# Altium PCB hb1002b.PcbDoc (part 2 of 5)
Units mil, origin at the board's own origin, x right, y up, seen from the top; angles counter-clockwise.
Board outline 2756 x 3549 mil, 2 copper layers (Top Layer, Bottom Layer); 120 components, 136 nets, 498 pads, 328 vias.
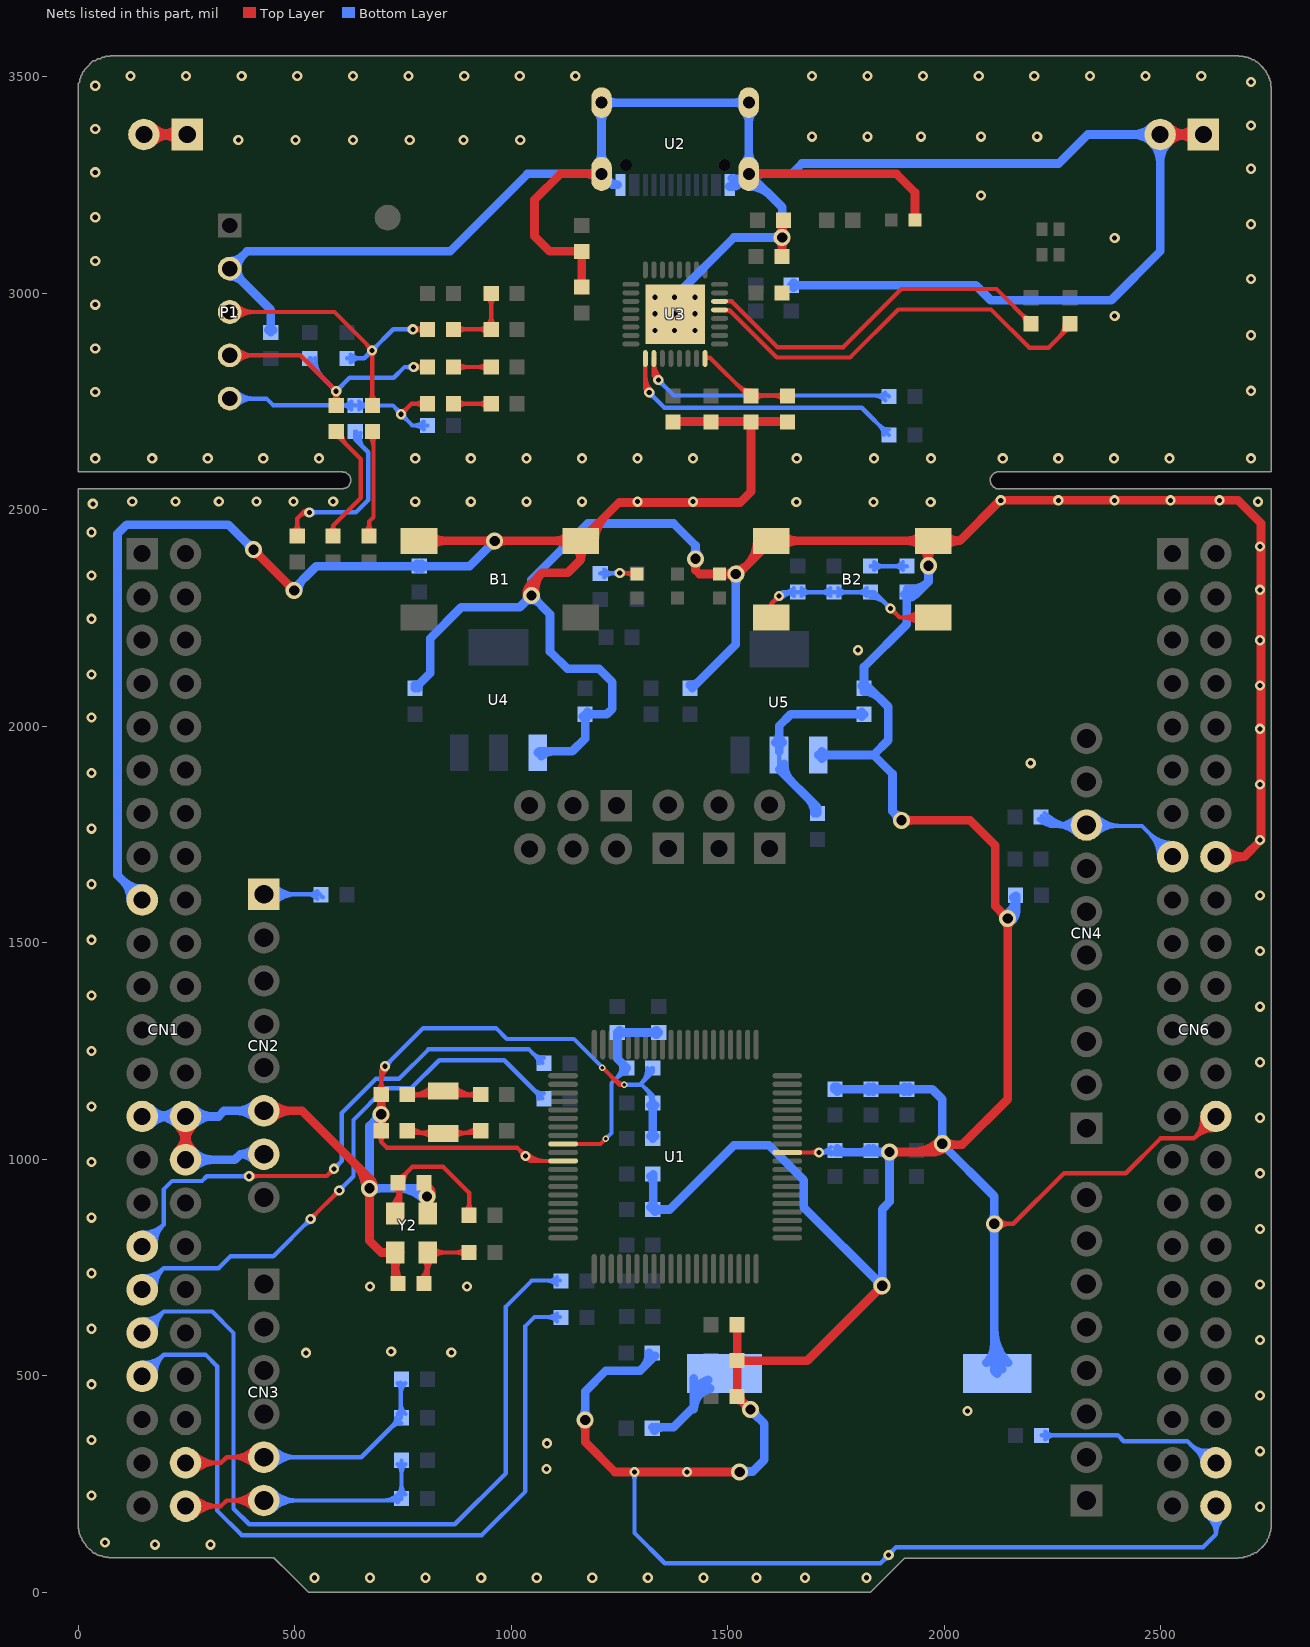
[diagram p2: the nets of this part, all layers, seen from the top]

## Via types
v1: diameter 23.62, hole 11.81, Top Layer to Bottom Layer, tented both sides, 276 vias
v2: diameter 39.37, hole 23.62, Top Layer to Bottom Layer, tented both sides, 27 vias
v3: diameter 15, hole 8, Top Layer to Bottom Layer, tented both sides, 25 vias

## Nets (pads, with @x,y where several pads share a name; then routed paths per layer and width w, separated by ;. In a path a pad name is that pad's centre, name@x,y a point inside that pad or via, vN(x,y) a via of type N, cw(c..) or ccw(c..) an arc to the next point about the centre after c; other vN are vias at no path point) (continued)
GND: B1.1 B1.2 B2.1 B2.2 BT1.2 C1.1 C2.2 C3.1 C4.2 C5.1 C6.1 C9.2 C11.2 C12.2 C13.2 C14.2 C15.2 C16.2 C17.2 C18.2 C19.2 C20.1 C21.1 C22.1 C23.1 C24.1 C25.1 C26.1 C27.1 C28.1 C29.2 C30.2 C31.1 C32.2 C34.1 C35.2 C36.2 CN1.17 CN1.27 CN1.28 CN1.30 CN2.6 CN2.7 CN6.16 CN6.28 CN6.46 D3.2 D4.2 JP2.1 JP2.2 JP3.1 JP3.2 P1.2 R5.2 R11.2 R25.2 R28.1 U1.11 U1.51 U2.1 U2.2 U2.3 U2.4 U2.A1 U2.A12 U2.B1 U2.B12 U3.33 U4.1 U5.1 Y2.2 Y2.4 | length 32956.4
  Top Layer w10: CN1.30@248,999 CN1.30@251,996 ; CN2.7@424,996 CN2.7@428,1000 ; C5.1@691.16,1158.84 ccw(c669.82,1180.18) 700,1180.18 ccw(c730.18,1180.18) C5.1@708.84,1158.84 ; C6.1@692.19,1056.24 cw(c679.21,1040) 700,1040 ; C6.1@700,1056 700,1040 ; C5.1@700,1140 C5.1@700,1150 700,1206 v1(709,1215) v1@709,1219 ; 700,1176.83 cw(c747.17,1176.83) v1@713.82,1210.18 ; 700,1200.97 cw(c723.03,1200.97) v1@706.75,1217.25 ; C6.1@707.81,1056.24 ccw(c720.79,1040) 700,1040 ; Y2.4@810,883.68 Y2.4@818.4,875.28 ; v1@1026.19,1008 ccw(c1009.75,1008) 1021.37,1019.63 ccw(c1033,1031.25) v1@1033,1014.81 ; v1@1030.75,1005.75 ccw(c1053.89,1028.89) 1053.89,996.16 ; v1@1033,1001.19 cw(c1033,984.75) 1044.63,996.37 cw(c1056.25,1008) v1@1039.81,1008 ; v1@1037.82,1012.82 ccw(c1078.03,1053.03) 1078.03,996.16 ; U1.11@1120.14,996.16 1044.84,996.16 v1(1033,1008) 1013.9,1027.1 712.9,1027.1 700,1040 ; B1.2@1155.58,2428.58 B1.2@1161.01,2428.58 ; B1.2@1173.58,2428.58 B1.2@1174.58,2428.58 ; v3(1211,1212) 1251,1172 v3(1261,1172) ; 1239.66,1183.34 ccw(c1261,1204.68) v3@1261,1174.5 ; U1.51@1637.86,1015.84 v1@1711,1015.84 ; 1694.18,1015.84 ccw(c1694.18,1032.82) v1@1706.18,1020.82 ; 1694.94,1015.84 cw(c1694.94,999.94) v1@1706.18,1011.18 ; v2(2116,851) 2160,851 2277,968 2419.58,968 2500,1048.42 2577.42,1048.42 ; v2@2126.38,840.62 cw(c2151.45,815.55) 2151.45,851 cw(c2151.45,886.45) v2@2126.38,861.38 ; CN6.28@2596.61,1097.67 cw(c2530.95,1094.89) 2577.42,1048.42 ; CN6.28@2606.6,1098.09 cw(c2561.84,1096.2) 2593.52,1064.52 cw(c2625.2,1032.84) CN6.28@2627.09,1077.6 ; CN6.28@2626.67,1067.61 ccw(c2623.89,1001.95) 2577.42,1048.42 ; CN6.28@2628,1099 2577.42,1048.42
  Top Layer w20: JP3.2@152,3367 JP3.1@252,3367 ; JP3.2@170.68,3348.32 cw(c215.78,3303.22) 215.78,3367 cw(c215.78,3430.78) JP3.2@170.68,3385.68 ; CN1.30@229.32,1017.68 ccw(c184.22,1062.78) 248,1062.78 ccw(c311.78,1062.78) CN1.30@266.68,1017.68 ; CN1.28@229.32,1080.32 cw(c184.22,1035.22) 248,1035.22 cw(c311.78,1035.22) CN1.28@266.68,1080.32 ; JP3.1@233.32,3348.32 ccw(c188.22,3303.22) 188.22,3367 ccw(c188.22,3430.78) JP3.1@233.32,3385.68 ; CN1.30@248,999 CN1.28@248,1099 ; v2@405,2398.31 cw(c405,2374.93) 421.53,2391.47 cw(c438.07,2408) v2@414.69,2408 ; v2(405,2408) v2(499,2314) ; CN2.6@429,1112 517,1112 673,956 ; CN2.6@447.68,1093.32 cw(c492.78,1048.22) 492.78,1112 cw(c492.78,1175.78) CN2.6@447.68,1130.68 ; v2@489.31,2314 ccw(c465.93,2314) 482.47,2330.53 ccw(c499,2347.07) v2@499,2323.69 ; 640.2,988.8 cw(c584.41,933) v2@663.31,933 ; v2@666.15,926.15 cw(c649.62,909.62) 673,909.62 cw(c696.38,909.62) v2@679.85,926.15 ; v2@666.23,939.93 ccw(c650.54,956) 673,956 ; 674.35,954.65 cw(c652.69,933) v2@683.32,933 ; v2@679.77,939.93 cw(c695.46,956) 673,956 ; v2@693.15,1097.15 cw(c676.62,1080.62) 700,1080.62 cw(c723.38,1080.62) v2@706.85,1097.15 ; v2@693.15,1110.85 ccw(c676.62,1127.38) 700,1127.38 ccw(c723.38,1127.38) v2@706.85,1110.85 ; C6.1@694.7,1071.3 ccw(c681.89,1084.11) 700,1084.11 ccw(c718.11,1084.11) C6.1@705.3,1071.3 ; C5.1@694.7,1144.7 cw(c681.89,1131.89) 700,1131.89 cw(c718.11,1131.89) C5.1@705.3,1144.7 ; C6.1@700,1056 C6.1@700,1066 C5.1@700,1140 ; Y2.2@724.36,772.55 cw(c704.46,752.65) 732.6,752.65 cw(c760.73,752.65) Y2.2@740.84,772.55 ; Y2.2@724.36,776.48 ccw(c704.46,756.59) 704.46,784.72 ccw(c704.46,812.86) Y2.2@724.36,792.96 ; 732.6,746.56 ccw(c772.56,746.56) C12.2@744.3,718.3 ; C12.2@739,713 732.6,719.4 Y2.2@732.6,784.72 ; Y2.2@743.6,784.72 Y2.2@732.6,784.72 ; B1.1@786.99,2428.58 B1.2@1155.58,2428.58 ; C11.2@793.7,940.7 cw(c763.03,910.03) v2@806.4,910.03 ; C11.2@799,946 C11.2@807.4,937.6 ; Y2.4@799.16,887.45 ccw(c781.68,904.93) v2@806.4,904.93 ; v2@799.15,907.15 cw(c781.65,889.65) Y2.4@806.4,889.65 ; v2@799.31,921 ccw(c783.44,937.6) 806.4,937.6 Y2.4@806.4,875.28 ; Y2.4@806.4,891.59 cw(c828.41,891.59) v2@812.85,907.15 ; v2@806.4,909.76 ccw(c837.95,909.76) Y2.4@815.64,887.45 ; C11.2@806.4,936.41 ccw(c828.41,936.41) v2@812.85,920.85 ; C11.2@809.89,935.11 cw(c792.87,918.09) v2@815.85,910.93 ; B1.1@813.68,2414.5 cw(c847.68,2380.49) 847.68,2428.58 cw(c847.68,2476.68) B1.1@813.68,2442.67 ; 937.21,2428.58 cw(c937.21,2403.21) v2@955.15,2421.15 ; 940.03,2428.58 ccw(c940.03,2449.97) v2@955.15,2434.85 ; v2@968.85,2421.15 cw(c986.79,2403.21) 986.79,2428.58 ; v2@968.85,2434.85 ccw(c983.97,2449.97) 983.97,2428.58 ; v2@1036.88,2299.99 cw(c1067.92,2306.16) 1045.54,2328.54 ; v2@1040.15,2308.85 ccw(c1023.62,2325.38) 1047,2325.38 ccw(c1070.38,2325.38) v2@1053.85,2308.85 ; v2(1047,2302) 1047,2330 1072,2355 ; v2@1056.5,2303.89 cw(c1112.05,2314.95) 1072,2355 ; B1.2@1134.32,2414.5 ccw(c1100.32,2380.49) 1100.32,2428.58 ccw(c1100.32,2476.68) B1.2@1134.32,2442.67 ; B1.2@1147.97,2413.52 cw(c1123.32,2385.01) 1161.01,2385.01 ; C29.2@1157.7,3020.3 ccw(c1144.89,3033.11) 1163,3033.11 ccw(c1181.11,3033.11) C29.2@1168.3,3020.3 ; C31.1@1157.7,3102.3 cw(c1144.89,3115.11) 1144.89,3097 cw(c1144.89,3078.89) 1157.7,3091.7 cw(c1144.89,3078.89) 1163,3078.89 cw(c1181.11,3078.89) C31.1@1168.3,3091.7 ; C29.2@1163,3007 C31.1@1163,3097 1089,3097 1054,3132 1054,3216 1114,3276 U2.1@1208.84,3276 ; v2@1164.15,391.15 cw(c1147.62,374.62) 1171,374.62 cw(c1194.38,374.62) v2@1177.85,391.15 ; v2(1171,398) 1171,347 1240,278 v1(1285,278) v1(1406,278) v2(1528,278) v2@1529,278 ; B1.2@1173.58,2428.58 B1.2@1161.01,2428.58 ; B1.2@1174.04,2413.52 ccw(c1198.7,2385.01) 1161.01,2385.01 ; B1.2@1193.53,2428.58 cw(c1272.04,2428.58) 1216.52,2484.1 ; U2.1@1199.21,3266.37 ccw(c1175.96,3243.11) 1175.96,3276 ccw(c1175.96,3308.89) U2.1@1199.21,3285.63 ; C21.1@1369,2704 1459,2704 1554,2704 C28.1@1633,2704 ; C21.1@1379.3,2697.7 cw(c1394.52,2682.48) 1394.52,2704 ; v2(1426,2387) 1426,2361 1435,2352 D3.2@1481,2352 v2(1519,2352) 1524.41,2352 B2.1@1600.99,2428.58 B2.2@1975.01,2428.58 ; 1441.48,2704 cw(c1441.48,2682.48) C20.1@1456.7,2697.7 ; C20.1@1467.3,2697.7 cw(c1482.52,2682.48) 1482.52,2704 ; v2@1512.15,2345.15 ccw(c1495.62,2328.62) 1495.62,2352 ccw(c1495.62,2375.38) v2@1512.15,2358.85 ; C13.2@1516.7,457.3 ccw(c1503.89,470.11) 1522,470.11 ccw(c1540.11,470.11) C13.2@1527.3,457.3 ; C14.2@1516.7,529.7 cw(c1503.89,516.89) 1522,516.89 cw(c1540.11,516.89) 1527.3,529.7 cw(c1540.11,516.89) 1540.11,535 cw(c1540.11,553.11) 1527.3,540.3 cw(c1540.11,553.11) 1522,553.11 cw(c1503.89,553.11) C14.2@1516.7,540.3 ; C15.2@1516.7,612.7 cw(c1503.89,599.89) 1522,599.89 cw(c1540.11,599.89) C15.2@1527.3,612.7 ; v2@1519,2361.69 ccw(c1519,2398.13) 1544.77,2372.36 ; v2@1521.15,271.15 ccw(c1504.62,254.62) 1504.62,278 ccw(c1504.62,301.38) v2@1521.15,284.85 ; C13.2@1522,444.5 cw(c1522,426.39) 1534.8,439.2 cw(c1547.61,452) C13.2@1529.5,452 ; C15.2@1522,618 C14.2@1522,535 ; 1533.48,2704 cw(c1533.48,2682.48) 1548.7,2697.7 cw(c1535.89,2684.89) 1554,2684.89 cw(c1572.11,2684.89) 1559.3,2697.7 cw(c1574.52,2682.48) 1574.52,2704 ; C13.2@1534.76,439.24 ccw(c1553,457.48) v2@1553,431.68 ; C13.2@1537.17,436.82 cw(c1522.35,422) v2@1543.31,422 ; 1545.48,2373.07 ccw(c1489.96,2428.58) B2.1@1568.47,2428.58 ; U2.2@1549,3276 1890,3276 1933,3233 D4.2@1933,3169 ; v2@1550,424 C13.2@1522,452 C14.2@1522,535 ; C22.1@1554,2703 1554,2542 1529,2517 1249.43,2517 B1.2@1161.01,2428.58 ; U2.2@1558.63,3266.37 cw(c1581.89,3243.11) 1581.89,3276 cw(c1581.89,3308.89) U2.2@1558.63,3285.63 ; 1617.48,2704 cw(c1617.48,2682.48) C28.1@1632.7,2697.7 ; v2@1619.15,3122.15 cw(c1602.62,3105.62) 1626,3105.62 cw(c1649.38,3105.62) v2@1632.85,3122.15 ; v2@1619.15,3135.85 ccw(c1602.62,3152.38) 1626,3152.38 ccw(c1649.38,3152.38) v2@1632.85,3135.85 ; C32.2@1620.7,3090.3 ccw(c1607.89,3103.11) 1626,3103.11 ccw(c1644.11,3103.11) C32.2@1631.3,3090.3 ; C32.2@1626,3086 C34.1@1626,3169 ; v2@1626,3143.65 cw(c1654.35,3143.65) C34.1@1634.3,3163.7 ; B2.1@1627.68,2414.5 cw(c1661.68,2380.49) 1661.68,2428.58 cw(c1661.68,2476.68) B2.1@1627.68,2442.67 ; v2@1847.31,708 cw(c1823.93,708) 1840.47,691.47 cw(c1857,674.93) v2@1857,698.32 ; v2(1857,708) 1684,535 C14.2@1522,535 ; v2@1873,1017 1979,1017 1996,1034 2042,1034 2147,1139 v2(2147,1556) 2118,1585 2118,1725 2060,1783 v2(1902,1783) ; v2@1880.85,1010.15 cw(c1897.38,993.62) 1897.38,1017 cw(c1897.38,1040.38) v2@1880.85,1023.85 ; v2@1908.85,1776.15 cw(c1925.38,1759.62) 1925.38,1783 cw(c1925.38,1806.38) v2@1908.85,1789.85 ; 1926.75,1017 ccw(c1926.75,1105.25) v2@1989.15,1042.85 ; B2.2@1948.32,2442.67 cw(c1914.32,2476.68) 1914.32,2428.58 cw(c1914.32,2380.49) 1948.32,2414.5 cw(c1910.48,2376.65) v2@1964,2376.65 ; v2@1957.15,2377.85 ccw(c1940.62,2394.38) 1964,2394.38 ccw(c1987.38,2394.38) v2@1970.85,2377.85 ; v2(1964,2371) 1964,2417.57 B2.2@1975.01,2428.58 ; v2@1964,2384.33 cw(c2006.66,2384.33) B2.2@1976.5,2414.5 ; 1975.03,1017 ccw(c1975.03,1056.97) v2@2003.29,1028.71 ; B2.2@2001.69,2414.5 cw(c2035.7,2380.49) 2035.7,2428.58 cw(c2035.7,2476.68) B2.2@2001.69,2442.67 ; v2@2002.85,1042.85 ccw(c2024.21,1064.21) 2024.21,1034 ; v2@2137.31,1556 ccw(c2113.93,1556) 2130.47,1572.53 ccw(c2147,1589.07) v2@2147,1565.68 ; v2@2140.15,1549.15 cw(c2123.62,1532.62) 2147,1532.62 cw(c2170.38,1532.62) v2@2153.85,1549.15 ; JP2.2@2499,3367 JP2.1@2599,3367 ; JP2.2@2517.68,3348.32 cw(c2562.78,3303.22) 2562.78,3367 cw(c2562.78,3430.78) JP2.2@2517.68,3385.68 ; JP2.1@2580.32,3348.32 ccw(c2535.22,3303.22) 2535.22,3367 ccw(c2535.22,3430.78) JP2.1@2580.32,3385.68 ; CN6.16@2628,1699 2693.34,1699 2732,1737.66 2732,1866 2732,1994.34 2732,2094.34 2732,2199 2732,2315.34 2732,2415.34 2732,2469 2679,2522 v1(2636,2522) v1(2523,2522) v1(2393.49,2522) v1(2263.91,2522) 2130,2522 2036.58,2428.58 B2.2@1975.01,2428.58 ; CN6.16@2646.68,1680.32 cw(c2691.78,1635.22) 2691.78,1699 cw(c2691.78,1762.78) CN6.16@2646.68,1717.68 ; 673,956 v2(673,933) 673,812 700.28,784.72 Y2.2@732.6,784.72 ; 1072,2355 1131,2355 1161.01,2385.01 ; 1161.01,2385.01 B1.2@1161.01,2428.58 ; 1426,2363.62 ccw(c1402.62,2363.62) 1419.15,2380.15 cw(c1402.62,2363.62) 1426,2363.62 ; 1426,2363.62 cw(c1449.38,2363.62) 1432.85,2380.15 ccw(c1449.38,2363.62) 1426,2363.62
  Bottom Layer w10: CN2.6@427,1099 CN2.6@428,1100 ; v1(709,1215) 797,1303 965,1303 990,1278 1145,1278 v3(1211,1212) ; v1@709,1221.81 ccw(c709,1238.25) 720.63,1226.63 ccw(c732.25,1215) v1@715.81,1215 ; v3(1261,1172) 1297,1172 ; v1@1280.18,273.18 cw(c1268.56,261.56) 1285,261.56 cw(c1301.44,261.56) v1@1289.82,273.18 ; v1(1285,278) 1285,137 1355,67 1853,67 v1(1872,86) 1872,87 1889,104 2598,104 2628,134 ; 1289,512 1291,512 ; 1301.5,1176.5 ccw(c1269.94,1208.06) C24.1@1314.52,1210.36 ; 1310.71,1163.29 cw(c1277.42,1130) C4.2@1324.5,1130 ; 1317.4,1192.4 ccw(c1300.19,1209.62) C24.1@1324.5,1210.87 ; C1.1@1327,884 1328,884 C1.1@1328,883 ; C4.2@1327,1130 1327,1147 1302,1172 1297,1172 ; C24.1@1327,1211 1327,1202 1297,1172 ; v2@1549,425 v2@1551,425 ; v1@1715.82,1011.18 cw(c1727.44,999.56) 1727.44,1016 cw(c1727.44,1032.44) v1@1715.82,1020.82 ; 1727.48,1016 cw(c1727.48,999.48) C18.2@1739.16,1011.16 ; C18.2@1738.7,1028.35 cw(c1711,1053.23) v1(1711,1016) 1743,1016 1748,1011 C18.2@1753,1016 ; v1@1865.19,86 cw(c1848.75,86) 1860.37,74.37 cw(c1872,62.75) v1@1872,79.19 ; v1@1872,92.81 ccw(c1872,106.84) 1881.92,96.92 ; v1@1878.81,86 cw(c1897.67,86) 1884.33,99.33 ; CN6.46@2608.48,174.38 cw(c2576.47,134) 2628,134 ; CN6.46@2614.7,182.22 cw(c2592.88,154.69) 2628,154.69 cw(c2663.12,154.69) CN6.46@2641.3,182.22 ; CN6.46@2628,201 CN6.46@2628,199 2628,134 ; CN6.46@2647.52,174.38 ccw(c2679.53,134) 2628,134
  Bottom Layer w20: CN1.17@121.58,1599 ccw(c57.81,1599) 102.9,1644.1 ccw(c148,1689.19) CN1.17@148,1625.42 ; CN1.27@148,1099 CN1.28@248,1099 324,1099 337,1112 CN2.6@429,1112 ; CN1.17@148,1599 91,1656 91,2445 112,2466 347,2466 v2(405,2408) ; CN1.27@166.68,1080.32 cw(c211.78,1035.22) 211.78,1099 cw(c211.78,1162.78) CN1.27@166.68,1117.68 ; CN1.28@229.32,1080.32 ccw(c184.22,1035.22) 184.22,1099 ccw(c184.22,1162.78) CN1.28@229.32,1117.68 ; CN1.30@248,999 362,999 375,1012 ; CN1.30@266.68,980.32 cw(c311.78,935.22) 311.78,999 cw(c311.78,1062.78) CN1.30@266.68,1017.68 ; CN1.28@266.68,1080.32 cw(c311.78,1035.22) 311.78,1099 cw(c311.78,1162.78) CN1.28@266.68,1117.68 ; P1.2@350,3039.5 cw(c350,2997.25) 379.87,3027.13 cw(c409.75,3057) 367.5,3057 cw(c409.75,3057) 379.87,3086.87 cw(c350,3116.75) P1.2@350,3074.5 ; v2@395.31,2408 ccw(c371.93,2408) 388.47,2424.53 ccw(c405,2441.07) v2@405,2417.69 ; CN2.7@408.14,995.79 ccw(c375,970.02) 375,1012 ; CN2.7@408.14,1028.21 cw(c375,1053.98) 375,1012 ; CN2.6@410.32,1093.32 ccw(c365.22,1048.22) 365.22,1112 ccw(c365.22,1175.78) CN2.6@410.32,1130.68 ; CN2.7@429,1012 375,1012 ; R28.1@439.7,2915.3 ccw(c426.9,2928.1) 445,2928.1 ccw(c463.11,2928.11) R28.1@450.3,2915.3 ; R28.1@445,2910 445,2962 P1.2@350,3057 390,3097 859,3097 1038,3276 U2.1@1208.84,3276 ; v2@494,2314 550,2370 C2.2@788,2370 904,2370 v2(962,2428) ; v2@508.69,2314 cw(c544.14,2314) 519.07,2339.07 ; v2@666.15,939.85 ccw(c649.62,956.38) 673,956.38 ccw(c696.38,956.38) 679.85,939.85 ccw(c696.38,956.38) 696.38,933 ccw(c696.38,909.62) v2@679.85,926.15 ; v2@690.31,1104 cw(c666.93,1104) 683.47,1087.47 cw(c700,1070.93) v2@700,1094.32 ; v2(700,1104) 673,1077 v2(673,933) 787,933 v2(806,914) ; 736.75,933 cw(c736.75,844.75) v2@799.15,907.15 ; C23.1@778,2088 813,2123 813,2203 885,2275 1020,2275 v2(1047,2302) ; C23.1@778,2095.5 ccw(c778,2113.61) 790.8,2100.8 ccw(c803.61,2088) C23.1@785.5,2088 ; C2.2@782.7,2364.7 ccw(c769.89,2351.89) 769.89,2370 ccw(c769.89,2388.11) C2.2@782.7,2375.3 ; 785.03,933 cw(c785.03,893.03) v2@813.29,921.29 ; C2.2@793.3,2364.7 cw(c806.11,2351.89) 806.11,2370 cw(c806.11,2388.11) C2.2@793.3,2375.3 ; v2@952.31,2428 cw(c928.93,2428) 945.47,2411.47 cw(c962,2394.93) v2@962,2418.31 ; v2@1037.31,2302 cw(c1013.93,2302) 1030.47,2285.47 cw(c1047,2268.93) 1047,2292.31 cw(c1047,2268.93) 1063.53,2285.47 cw(c1080.07,2302) v2@1056.69,2302 ; v2@1040.15,2308.85 ccw(c1023.62,2325.38) 1047,2325.38 ccw(c1070.38,2325.38) v2@1053.85,2308.85 ; U4.1@1061.55,1938.95 1065.1,1942.5 1141.5,1942.5 1171,1972 C25.1@1171,2028 1221,2028 1234,2041 1234,2102 1203,2133 1130,2133 1090,2173 1090,2259 v2(1047,2302) ; U4.1@1069.79,1930.71 cw(c1098.25,1902.26) 1098.25,1942.5 ; v2@1164.15,404.85 ccw(c1147.62,421.38) 1171,421.38 ccw(c1194.38,421.38) v2@1177.85,404.85 ; C25.1@1165.7,2022.7 cw(c1152.89,2009.89) 1171,2009.89 cw(c1189.11,2009.89) 1176.3,2022.7 cw(c1189.1,2009.9) 1189.1,2028 cw(c1189.11,2046.11) C25.1@1176.3,2033.3 ; v2(1171,398) 1171,464 1219,512 1298,512 R11.2@1332.5,546.5 ; U2.1@1199.21,3266.37 ccw(c1175.96,3243.11) 1175.96,3276 ccw(c1175.96,3308.89) U2.1@1199.21,3285.63 ; U2.1@1199.21,3301.38 ccw(c1175.96,3324.63) 1208.84,3324.63 ccw(c1241.73,3324.63) U2.1@1218.48,3301.38 ; U2.3@1199.21,3419.12 cw(c1175.96,3395.87) 1208.84,3395.87 cw(c1241.73,3395.87) U2.3@1218.48,3419.12 ; U2.3@1218.48,3430.93 cw(c1241.73,3407.68) 1241.73,3440.57 cw(c1241.73,3473.45) U2.3@1218.48,3450.2 ; U2.1@1220.94,3266.51 ccw(c1246.43,3279.7) 1246.43,3251 1234,3251 1221.43,3263.57 1221.43,3276 U2.1@1208.84,3276 ; 1304.5,518.5 ccw(c1270.69,552.31) R11.2@1318.5,552.91 ; C1.1@1321.7,889.3 ccw(c1306.48,904.52) 1328,904.52 ; C3.1@1321.7,960.7 cw(c1306.48,945.48) 1328,945.48 ; C9.2@1321.7,1053.3 ccw(c1308.89,1066.11) 1327,1066.11 ccw(c1345.11,1066.11) C9.2@1332.3,1053.3 ; C4.2@1321.7,1124.7 cw(c1308.89,1111.89) 1327,1111.89 cw(c1345.11,1111.89) C4.2@1332.3,1124.7 ; C9.2@1327,1048 C4.2@1327,1130 ; C3.1@1328,965 1328,884 1366.5,884 1515,1032.5 1595.5,1032.5 1676,952 1676,889 v2(1857,708) 1857,885 1874,902 1874,939 ; C1.1@1332.3,878.7 cw(c1345.11,865.89) 1345.11,884 cw(c1345.11,902.11) C1.1@1332.3,889.3 ; v1(1377,2991) 1515,3129 v2(1626,3129) 1626,3199 U2.2@1549,3276 ; C26.1@1413,2095.5 ccw(c1413,2125.68) 1434.34,2104.34 ; C26.1@1418,2088 1519,2189 v2(1519,2352) ; v2@1419.15,2393.85 ccw(c1402.62,2410.38) 1426,2410.38 ccw(c1449.38,2410.38) v2@1432.85,2393.85 ; v2(1426,2387) 1426,2418 1375.31,2468.69 1176.69,2468.69 1047,2339 v2(1047,2302) ; U2.B1@1503.78,3247.04 ccw(c1510.11,3267.79) 1525.45,3252.45 ; U2.A12@1509.62,3266.17 ccw(c1521.12,3303.87) U2.2@1549,3276 ; v2@1512.15,2345.15 cw(c1495.62,2328.62) 1519,2328.62 cw(c1542.38,2328.62) v2@1525.85,2345.15 ; v2@1529,279 1558,279 1585,306 1585,389 v2@1549,425 ; v2@1534.85,271.15 cw(c1553.8,252.2) 1553.8,279 ; v2@1534.85,284.85 ccw(c1548.97,298.97) 1548.97,279 ; U2.2@1536.85,3266.4 cw(c1510.81,3279.58) U2.A12@1510.81,3250.4 1523.4,3250.4 U2.2@1549,3276 ; U2.2@1539.37,3301.38 ccw(c1516.11,3324.63) 1549,3324.63 ccw(c1581.89,3324.63) U2.2@1558.63,3301.38 ; U2.4@1539.37,3419.12 cw(c1516.11,3395.87) 1549,3395.87 cw(c1581.89,3395.87) U2.4@1558.63,3419.12 ; U2.4@1539.37,3430.93 ccw(c1516.11,3407.68) 1516.11,3440.57 ccw(c1516.11,3473.45) U2.4@1539.37,3450.2 ; U2.2@1549,3246.63 cw(c1549,3175.72) 1599.14,3225.86 ; v2@1553,412.32 cw(c1553,391.35) 1567.83,406.17 ; U2.2@1558.63,3266.37 cw(c1581.89,3243.11) 1581.89,3276 cw(c1581.89,3308.89) U2.2@1558.63,3285.63 ; v2@1562.68,422 ccw(c1588.48,422) 1570.24,403.76 ; v2@1619.15,3122.15 ccw(c1602.62,3105.62) 1602.62,3129 ccw(c1602.62,3152.38) 1619.15,3135.85 ccw(c1602.62,3152.38) 1626,3152.38 ccw(c1649.38,3152.38) v2@1632.85,3135.85 ; C30.2@1647,3019 2073,3019 2108,2984 2386,2984 2499,3097 JP2.2@2499,3367 2332,3367 2265,3300 1672,3300 1648,3276 U2.2@1549,3276 ; C30.2@1652.3,3013.7 cw(c1665.11,3000.89) 1665.11,3019 cw(c1665.11,3037.11) C30.2@1652.3,3024.3 ; U5.1@1709.55,1933.95 1836.95,1933.95 ; U5.1@1717.79,1925.71 cw(c1737.69,1905.82) 1737.69,1933.95 cw(c1737.69,1962.09) U5.1@1717.79,1942.19 ; C17.2@1746,1162 1747,1162 C17.2@1747,1167 ; C17.2@1748,1162 C19.2@1831,1162 1858,1162 C36.2@1914,1162 1972.5,1162 1995.5,1139 v2@1995.5,1036 ; C18.2@1753,1016 1831,1016 1874,1016 1874,939 ; C18.2@1753.3,1025.3 ccw(c1775.76,1047.76) 1775.76,1016 ; C17.2@1753.3,1156.7 cw(c1766.11,1143.89) 1766.11,1162 cw(c1766.11,1180.11) C17.2@1753.3,1167.3 ; 1803.24,1016 ccw(c1803.24,1047.76) C16.2@1825.7,1025.3 ; C27.1@1809.7,2093.3 ccw(c1796.89,2106.11) 1815,2106.11 ccw(c1833.11,2106.11) C27.1@1820.3,2093.3 ; C27.1@1815,2080.5 cw(c1815,2031.01) 1850,2066.01 ; C27.1@1815,2088 1815,2137 1914,2236 R5.2@1914,2310 1940,2310 1964,2334 ; C19.2@1825.7,1156.7 ccw(c1812.89,1143.89) 1812.89,1162 ccw(c1812.89,1180.11) C19.2@1825.7,1167.3 ; C27.1@1828,2088 1871,2045 1871,1968 1836.95,1933.95 ; C16.2@1836.3,1025.3 ccw(c1858.76,1047.76) v2@1858.76,1016 ; v2@1847.31,708 ccw(c1823.93,708) 1840.47,724.53 ccw(c1857,741.07) v2@1857,717.68 ; C16.2@1848.2,1016 ccw(c1848.2,1042.8) v2@1867.15,1023.85 ; v2@1850.15,714.85 ccw(c1833.62,731.38) 1857,731.38 ccw(c1880.38,731.38) v2@1863.85,714.85 ; 1853.03,1016 cw(c1853.03,996.03) 1867.15,1010.15 cw(c1850.62,993.62) 1874,993.62 cw(c1897.38,993.62) v2@1880.85,1010.15 ; 1874,907 1874,939 ; v2@1892.31,1783 ccw(c1868.93,1783) 1885.47,1799.53 ccw(c1902,1816.07) v2@1902,1792.68 ; v2(1902,1783) 1880.95,1804.05 1880.95,1889.95 1836.95,1933.95 ; C36.2@1908.7,1156.7 ccw(c1895.89,1143.89) 1895.89,1162 ccw(c1895.89,1180.11) C36.2@1908.7,1167.3 ; R5.2@1908.7,2304.7 cw(c1895.89,2291.89) 1914,2291.89 cw(c1932.11,2291.89) 1919.3,2304.7 cw(c1932.11,2291.89) 1932.11,2310 cw(c1932.11,2328.11) R5.2@1919.3,2315.3 ; R5.2@1912.34,2297.61 ccw(c1915.99,2324.83) 1935.41,2305.41 ; R5.2@1915,2317.43 ccw(c1922.76,2375.24) 1964,2334 ; C36.2@1919.3,1156.7 cw(c1932.11,1143.89) 1932.11,1162 cw(c1932.11,1180.11) C36.2@1919.3,1167.3 ; v2@1957.15,2364.15 cw(c1940.62,2347.62) 1964,2347.62 cw(c1987.38,2347.62) v2@1970.85,2364.15 ; v2@1964,2372 v2(1964,2371) 1964,2334 ; v2@1989.15,1042.85 ccw(c1973.83,1058.17) 1995.5,1058.17 ; 1995.5,1060.59 ccw(c2020.59,1060.59) v2@2002.85,1042.85 ; v2@1996,1026.32 cw(c1996,1005.35) 2010.83,1020.17 ; v2@1996.5,1034.5 2116,915 v2(2116,851) 2116,511.92 BT1.2@2122.92,505 ; v2@2005.68,1036 ccw(c2031.48,1036) 2013.24,1017.76 ; BT1.2@2097.98,529.94 ccw(c2054.47,573.45) 2116,573.45 ; v2@2109.15,844.15 cw(c2092.62,827.62) 2116,827.62 cw(c2139.38,827.62) v2@2122.85,844.15 ; v2@2109.15,857.85 ccw(c2092.62,874.38) 2116,874.38 ccw(c2139.38,874.38) v2@2122.85,857.85 ; 2116,558.59 ccw(c2176.51,558.59) BT1.2@2133.72,515.8 ; 2116,606.87 ccw(c2224.79,606.87) BT1.2@2147.86,529.94 ; v2@2141.7,1564.11 ccw(c2112.39,1609) 2166,1609 2166,1575 v2(2147,1556) ; v2@2152.64,1547.36 ccw(c2136.52,1572.05) 2166,1572.05 ; R25.2@2159.7,1604.7 cw(c2144.48,1589.48) 2166,1589.48 ; JP2.2@2480.32,3385.68 cw(c2435.22,3430.78) 2435.22,3367 cw(c2435.22,3303.22) 2480.32,3348.32 cw(c2435.22,3303.22) 2499,3303.22 cw(c2562.78,3303.22) JP2.2@2517.68,3348.32 ; U2.1@1208.84,3276 U2.3@1208.84,3440.57 U2.4@1549,3440.57 U2.2@1549,3276 ; C19.2@1836.3,1156.7 cw(c1849.11,1143.89) 1849.11,1162 ; C19.2@1836.3,1156.7 cw(c1849.11,1143.89) 1849.11,1162 ; C19.2@1836.3,1156.7 cw(c1849.11,1143.89) 1849.11,1162 ; C19.2@1836.3,1167.3 ccw(c1849.11,1180.11) 1849.11,1162 ; C19.2@1836.3,1167.3 ccw(c1849.11,1180.11) 1849.11,1162 ; C19.2@1836.3,1167.3 ccw(c1849.11,1180.11) 1849.11,1162
  other v1: 545.82,33.66 674.16,33.66 802.49,33.66 930.83,33.66 1059.17,33.66 1187.5,33.66 1315.84,33.66 1444.17,33.66 1567,33.66 1679,33.66 1821,33.66 177.34,110 305.67,110 62,115 2730,197.64 31,223.64 1082,285 2730,325.97 1083,344 31,351.97 2054,419 2730,454.31 31,480.31 526,553 862,554 723,556 2730,582.64 31,608.64 674,706 898,706 2730,710.98 31,736.98 2730,839.32 31,865.32 2730,967.65 31,993.65 2730,1095.99 31,1121.99 2730,1224.32 31,1250.32 2730,1352.66 31,1378.66 2730,1480.99 31,1506.99 2730,1609.33 31,1635.33 2730,1737.66 31,1763.66 2730,1866 31,1892 2200,1915 2730,1994.34 31,2020.34 2730,2094.34 31,2120 1801,2176 2730,2199 31,2248.34 2730,2315.34 31,2348.34 2730,2415.34 31,2448.34 34,2514 1658.77,2518 1837.18,2518 1969.04,2518 125,2519.34 225,2519.34 325,2519.34 412,2519.34 497.65,2519.34 589,2519.34 778.67,2519 907.01,2519 1035.67,2519 1164.01,2519 1292.01,2519 1420.34,2519 2725,2519 2131,2522 39.57,2619 170.99,2619 299.33,2619 427.66,2619 556,2619 778.67,2619 907.01,2619 1035.67,2619 1164.01,2619 1292.01,2619 1420.34,2619 1659.77,2619 1838.18,2619 1970.04,2619 2135.57,2619 2263.91,2619 2392.25,2619 2520.58,2619 2709,2619 39.57,2772 2709,2774.99 39.57,2873 2709,2903.33 1332,2914 1377,2914 1425,2914 2394,2948 1332,2953 1377,2953 1425,2953 39.57,2974 1332,2991 1425,2991 2709,3033 39.57,3075 2394,3128 2709,3159.66 39.57,3176 2085,3226 39.57,3279.68 2709,3288 370,3354 502,3354 635,3354 766,3354 890,3354 1021,3354 1694.66,3362 1822.99,3362 1947,3362 2085,3362 2215,3362 39.57,3379.68 2709,3388 39.57,3479.68 2709,3488 120.66,3502 248.99,3502 377.66,3502 505.99,3502 634.66,3502 762.99,3502 891.66,3502 1019.99,3502 1148.33,3502 1694.66,3502 1822.99,3502 1951.33,3502 2079.99,3502 2208.33,3502 2336.99,3502 2465.33,3502 2594,3502
  other v2: 1553,422 1874,1017 1996,1036
HED_LINK_LEDG: R33.1 U3.5 | length 1037
  Top Layer w10: U3.5@1479.39,2961.84 1503.61,2961.84 1613.46,2852 1783,2852 1894,2963 2108.5,2963 2197,2874.5 2241.5,2874.5 R33.1@2291,2924 ; U3.5@1495.54,2961.33 cw(c1495.54,2940.59) 1510.2,2955.26 ; U3.5@1495.64,2961.34 cw(c1498.4,2948.55) 1507.65,2957.8 ; 2265.42,2898.42 ccw(c2233.84,2930) R33.1@2278.5,2930 ; R33.1@2279.9,2912.9 cw(c2291,2901.81) R33.1@2291,2917.5
HED_LINK_LEDR: R32.1 U3.6 | length 901.4
  Top Layer w10: U3.6@1479.39,2981.53 1509.38,2981.53 1614.91,2876 1767,2876 1901,3010 2121,3010 R32.1@2201,2930 ; R32.1@2188.5,2930 ccw(c2158.32,2930) 2179.66,2951.34 ccw(c2201,2972.68) R32.1@2201,2942.5
HED_LINK_RESET: R38.1 R50.2 | length 181.8
  Top Layer w10: R38.1@867,2745 R50.2@954,2745 ; R38.1@875.84,2736.16 cw(c897.18,2714.82) 897.18,2745 cw(c897.18,2775.18) R38.1@875.84,2753.84 ; R50.2@945.16,2736.16 ccw(c923.82,2714.82) 923.82,2745 ccw(c923.82,2775.18) R50.2@945.16,2753.84
HED_LINK_SWCLK: R41.1 R51.2 | length 181.8
  Top Layer w10: R41.1@867,2830 R51.2@954,2830 ; R41.1@875.84,2821.16 cw(c897.18,2799.82) 897.18,2830 cw(c897.18,2860.18) R41.1@875.84,2838.84 ; R51.2@945.16,2821.16 ccw(c923.82,2799.82) 923.82,2830 ccw(c923.82,2860.18) R51.2@945.16,2838.84
HED_LINK_SWDIO: R37.1 R42.2 R43.2 | length 440
  Top Layer w10: R37.1@867,2917 R42.2@954,2917 ; R37.1@875.84,2908.16 cw(c897.18,2886.82) 897.18,2917 cw(c897.18,2947.18) R37.1@875.84,2925.84 ; R42.2@945.16,2908.16 ccw(c923.82,2886.82) 923.82,2917 ccw(c923.82,2947.18) R42.2@945.16,2925.84 ; R43.2@945.16,2991.16 cw(c923.82,2969.82) 954,2969.82 cw(c984.18,2969.82) R43.2@962.84,2991.16 ; 954,2950 R42.2@954,2917 ; R43.2@954,3000 R42.2@954,2917 ; R42.2@945.16,2925.84 ccw(c923.82,2947.18) 954,2947.18 ; R42.2@945.16,2925.84 ccw(c923.82,2947.18) 954,2947.18 ; 954,2947.18 ccw(c984.18,2947.18) 962.84,2925.84 cw(c984.18,2947.18) 954,2947.18
HED_LINK_USART_RX: R39.1 U3.26 | length 739.1
  Top Layer w10: 1329.79,2816.96 ccw(c1356.96,2816.96) v1@1337.75,2797.75 ; U3.26@1329.79,2841.1 ccw(c1381.1,2841.1) v1@1344.82,2804.82 ; U3.26@1329.79,2849.64 1329.79,2810.21 v1(1340,2800) ; U3.26@1329.79,2851.61 U3.26@1330.96,2850.43
  Bottom Layer w10: v1@1340,2793.19 cw(c1340,2776.75) 1351.63,2788.37 cw(c1363.25,2800) v1@1346.81,2800 ; v1(1340,2800) 1376,2764 1871,2764 R39.1@1873,2762 ; 1838,2764 cw(c1838,2727) R39.1@1864.16,2753.16 ; 1847.65,2764 ccw(c1847.65,2787.35) R39.1@1864.16,2770.84
HED_LINK_USART_TX: R40.1 U3.25 | length 806.7
  Top Layer w10: 1310.1,2784.78 ccw(c1332.78,2784.78) v1@1316.75,2768.75 ; 1310.1,2808.92 ccw(c1356.92,2808.92) v1@1323.82,2775.82 ; U3.25@1310.1,2851.61 1310.1,2779.9 v1(1319,2771)
  Bottom Layer w10: v1@1319,2764.19 cw(c1319,2747.75) 1330.63,2759.37 cw(c1342.25,2771) v1@1325.81,2771 ; v1(1319,2771) 1354,2736 1810,2736 R40.1@1873,2673 ; R40.1@1860.5,2673 ccw(c1830.32,2673) 1851.66,2694.34 ccw(c1873,2715.68) R40.1@1873,2685.5
LINK_MCU_NRST: P1.5 R38.2 R46.2 R49.2 | length 953
  Top Layer w10: v1(746,2721) 770,2745 R38.2@807,2745 ; v1@746,2727.81 ccw(c746,2744.25) 757.63,2732.63 ccw(c769.25,2721) v1@752.81,2721 ; R38.2@798.16,2736.16 ccw(c776.82,2714.82) 776.82,2745 ccw(c776.82,2775.18) R38.2@798.16,2753.84
  Bottom Layer w10: P1.5@350,2757 435,2757 450,2742 639,2742 R49.2@640,2741 727,2741 v1@746,2722 ; P1.5@358.84,2748.16 cw(c380.18,2726.82) 380.18,2757 cw(c380.18,2787.18) P1.5@358.84,2765.84 ; P1.5@365.91,2741.09 cw(c404.32,2702.68) 404.32,2757 cw(c404.32,2811.32) P1.5@365.91,2772.91 ; 607.4,2742 cw(c607.4,2708.4) R49.2@631.16,2732.16 ; 612.24,2742 ccw(c612.24,2768.76) R49.2@631.16,2749.84 ; R49.2@648.84,2732.16 cw(c670.18,2710.82) 670.18,2741 cw(c670.18,2771.18) R49.2@648.84,2749.84 ; 733.67,2734.33 cw(c720.33,2721) v1@739.19,2721 ; 736.08,2731.92 ccw(c746,2741.84) v1@746,2727.81 ; v1@746,2714.19 cw(c746,2697.75) 757.63,2709.37 cw(c769.25,2721) v1@752.81,2721 ; v1(746,2721) 772,2695 R46.2@807,2695 ; R46.2@798.16,2686.16 ccw(c776.82,2664.82) 776.82,2695 ccw(c776.82,2725.18) R46.2@798.16,2703.84
LINK_MCU_SWCLK: P1.4 R41.2 R44.2 R47.2 | length 1117.7
  Top Layer w10: P1.4@350,2857 513,2857 v1(596,2774) R47.2@596,2741 ; P1.4@358.84,2848.16 cw(c380.18,2826.82) 380.18,2857 cw(c380.18,2887.18) P1.4@358.84,2865.84 ; P1.4@365.91,2841.09 cw(c404.32,2802.68) 404.32,2857 cw(c404.32,2911.32) P1.4@365.91,2872.91 ; R47.2@587.16,2749.84 ccw(c565.82,2771.18) 596,2771.18 ccw(c626.18,2771.18) R47.2@604.84,2749.84 ; v1@589.19,2774 ccw(c572.75,2774) 584.37,2785.63 ccw(c596,2797.25) v1@596,2780.81 ; v1@591.18,2769.18 cw(c579.55,2757.55) 596,2757.55 cw(c612.44,2757.56) v1@600.82,2769.18 ; v1@774,2830 R41.2@807,2830 ; v1@779.82,2825.18 cw(c791.45,2813.55) 791.45,2830 cw(c791.44,2846.44) v1@779.82,2834.82 ; R41.2@798.16,2821.16 ccw(c776.82,2799.82) 776.82,2830 ccw(c776.82,2860.18) R41.2@798.16,2838.84
  Bottom Layer w10: R44.2@535,2850 535,2835 v1(596,2774) 627,2805 729,2805 754,2830 v1(775,2830) ; R44.2@537.5,2850 ccw(c579.75,2850) 549.88,2820.12 ; R44.2@547.5,2850 ccw(c613.9,2850) 566.95,2803.05 ; v1@589.19,2774 ccw(c572.75,2774) 584.37,2785.63 ccw(c596,2797.25) 596,2780.81 ccw(c596,2797.25) 607.63,2785.63 ccw(c619.25,2774) v1@602.81,2774 ; v1@770.18,2825.18 ccw(c758.56,2813.56) 758.56,2830 ccw(c758.56,2846.44) v1@770.18,2834.82
LINK_MCU_SWDIO: P1.3 R37.2 R45.2 R48.2 | length 1137.6
  Top Layer w10: P1.3@350,2957 592,2957 679.67,2869.33 R48.2@679.67,2741.33 ; P1.3@358.84,2948.16 cw(c380.18,2926.82) 380.18,2957 cw(c380.18,2987.18) P1.3@358.84,2965.84 ; P1.3@365.91,2941.09 cw(c404.32,2902.68) 404.32,2957 cw(c404.32,3011.32) P1.3@365.91,2972.91 ; 665.96,2883.04 cw(c650.92,2868) v1@672.19,2868 ; 670.79,2878.21 ccw(c679,2886.43) v1@679,2874.81 ; R48.2@671.16,2749.84 ccw(c650.62,2770.38) 679.67,2770.38 ; v1@674.18,2863.18 cw(c660.94,2849.94) 679.67,2849.94 ; 679.67,2771.97 ccw(c710.97,2771.97) R48.2@688.84,2749.84 ; 679.67,2853.18 cw(c693.82,2853.18) v1@683.82,2863.18 ; v1(773,2917) R37.2@807,2917 ; v1@777.82,2912.18 cw(c789.45,2900.55) 789.45,2917 cw(c789.44,2933.44) v1@777.82,2921.82 ; R37.2@798.16,2908.16 ccw(c776.82,2886.82) 776.82,2917 ccw(c776.82,2947.18) R37.2@798.16,2925.84
  Bottom Layer w10: R45.2@621,2850 661,2850 v1(679,2868) 728,2917 v1(773,2917) ; R45.2@629.84,2841.16 cw(c651.18,2819.82) 651.18,2850 cw(c651.18,2880.18) R45.2@629.84,2858.84 ; v1@672.19,2868 cw(c655.75,2868) 667.37,2856.37 cw(c679,2844.75) v1@679,2861.19 ; v1@679,2874.81 ccw(c679,2891.25) 690.63,2879.63 ccw(c702.25,2868) v1@685.81,2868 ; v1@768.18,2912.18 ccw(c756.56,2900.56) 756.56,2917 ccw(c756.56,2933.44) v1@768.18,2921.82
MCU_NRST: R49.1 R54.1 | length 606.3
  Top Layer w10: R54.1@497.16,2448.84 ccw(c475.82,2470.18) 506,2470.18 ccw(c536.18,2470.18) R54.1@514.84,2448.84 ; R54.1@506,2440 506,2480 520,2494 ; 513,2487 cw(c522.39,2477.62) v1@530.06,2488.44 ; 515.76,2489.76 cw(c533.71,2471.81) v1@534.04,2497.19 ; 521.38,2495.38 cw(c529.34,2487.42) v1@535.84,2496.6 ; v1@528.64,2489.8 ccw(c520,2483.02) 520,2494 ; v1@528.64,2498.2 cw(c520,2504.98) 520,2494 ; v1(534,2494) 520,2494
  Bottom Layer w10: v1@534.48,2494.52 641.52,2494.52 670,2523 670,2633 640,2663 R49.1@640,2681 ; v1@538.82,2489.18 cw(c551.71,2476.29) 551.71,2494.52 ; v1@538.82,2498.82 ccw(c549.18,2509.18) 549.18,2494.52 ; R49.1@642.4,2680.29 ccw(c667.95,2672.73) 649.11,2653.89 ; R49.1@651.99,2677.45 ccw(c686.31,2667.31) 661,2642
MCU_SWCLK: R47.1 R52.1 | length 417.8
  Top Layer w10: R52.1@581.83,2450.24 ccw(c572.21,2464) 589,2464 ; R52.1@589,2431 589,2464 ; R47.1@596,2668.5 cw(c596,2655.22) R47.1@605.39,2664.61 ; R47.1@596,2681 596,2674 653,2617 653,2582 ; R52.1@596.16,2450.24 cw(c605.79,2464) 589,2464 ; R47.1@598.5,2681 ccw(c621.44,2681) R47.1@605.22,2664.78 ; R47.1@608.5,2681 ccw(c655.58,2681) 622.29,2647.71 ; 653,2602 653,2582 ; 589,2464 653,2528 653,2582
MCU_SWDIO: R48.1 R53.1 | length 359.8
  Top Layer w10: R53.1@663.16,2448.84 ccw(c641.82,2470.18) 672,2470.18 ccw(c702.18,2470.18) R53.1@680.84,2448.84 ; R48.1@671.16,2672.16 cw(c645,2646) 682,2646 ; R53.1@672,2431 672,2473 682,2483 682,2602 ; R48.1@680,2681 682,2679 682,2602 ; 682,2612 682,2602 ; 682,2655.65 cw(c705.35,2655.65) R48.1@688.84,2672.16
NetB2_3: B2.3 B2.4 C8.2 R4.1 R6.2 | length 1043.1
  Top Layer w10: B2.3@1595.2,2275.66 ccw(c1593.45,2282.99) 1600.99,2282.99 ; B2.3@1600.99,2251.42 1600.99,2282.99 ; B2.3@1606.78,2275.66 cw(c1608.53,2282.99) 1600.99,2282.99 ; v1@1612.19,2301 cw(c1595.75,2301) 1607.37,2289.37 cw(c1619,2277.75) v1@1619,2294.19 ; v1(1619,2301) 1600.99,2282.99 ; v1@1876,2265.19 cw(c1876,2246.33) 1889.33,2259.67 ; v1@1877,2272 1897.58,2251.42 B2.4@1975.01,2251.42 ; v1@1882.81,2272 ccw(c1896.84,2272) 1886.92,2262.08 ; B2.4@1944.79,2233.8 ccw(c1902.24,2191.25) 1902.24,2251.42 ccw(c1902.24,2311.58) B2.4@1944.79,2269.04 ; B2.4@1951.86,2240.87 ccw(c1926.39,2215.39) 1926.39,2251.42 ccw(c1926.39,2287.44) B2.4@1951.86,2261.97
  Bottom Layer w10: v1@1616.75,2303.25 cw(c1633.03,2286.97) 1633.03,2310 ; v1(1619,2301) 1628,2310 R4.1@1662,2310 R6.2@1746,2310 C8.2@1830,2310 1839,2310 v1@1876,2273 ; v1@1623.82,2296.18 cw(c1657.17,2262.83) R4.1@1657.17,2310 ; R4.1@1653.16,2301.16 ccw(c1631.82,2279.82) 1631.82,2310 ccw(c1631.82,2340.18) R4.1@1653.16,2318.84 ; R4.1@1670.84,2301.16 cw(c1692.18,2279.82) 1692.18,2310 cw(c1692.18,2340.18) R4.1@1670.84,2318.84 ; R6.2@1737.16,2301.16 ccw(c1715.82,2279.82) 1715.82,2310 ccw(c1715.82,2340.18) R6.2@1737.16,2318.84 ; R6.2@1754.84,2301.16 cw(c1776.18,2279.82) 1776.18,2310 cw(c1776.18,2340.18) R6.2@1754.84,2318.84 ; C8.2@1821.16,2301.16 ccw(c1799.82,2279.82) 1799.82,2310 ccw(c1799.82,2340.18) C8.2@1821.16,2318.84 ; C8.2@1830,2297.5 cw(c1830,2245.6) 1866.7,2282.3 ; C8.2@1830,2307.5 cw(c1830,2279.74) 1849.63,2299.37 ; 1863.67,2285.33 cw(c1850.33,2272) v1@1869.19,2272 ; 1866.08,2282.92 ccw(c1876,2292.84) v1@1876,2278.81
  other v1: 1876,2272
NetBT1_1: BT1.1 R34.2 | length 325.2
  Bottom Layer w20: R34.2@1326,381 1375,381 1422,428 BT1.1@1422,494 ; R34.2@1331.3,373.7 cw(c1348.93,356.07) 1348.93,381 ; 1422,422.49 cw(c1471.62,422.49) BT1.1@1459.95,470.71 ; 1422,447.9 cw(c1465.47,447.9) BT1.1@1455.25,490.15
NetC5_2: C5.2 R7.2 Y1.1 | length 434.1
  Top Layer w10: C5.2@760,1148.21 Y1.1@836.79,1148.21 ; C5.2@767.66,1148.21 ccw(c767.66,1217.81) Y1.1@816.87,1168.6 ; C5.2@768.84,1141.16 cw(c785.86,1124.14) 785.86,1148.21 ; C5.2@768.84,1158.84 ccw(c794.49,1184.5) 794.49,1148.21 ; 791.8,1148.21 ccw(c791.8,1193.67) Y1.1@823.94,1161.53 ; Y1.1@843,1148.21 R7.2@924.79,1148.21 ; Y1.1@862.06,1161.53 ccw(c894.2,1193.67) 894.2,1148.21 ; Y1.1@869.13,1168.6 ccw(c918.34,1217.81) R7.2@918.34,1148.21 ; 895.51,1148.21 ccw(c895.51,1184.5) R7.2@921.16,1158.84 ; 904.14,1148.21 cw(c904.14,1124.14) R7.2@921.16,1141.16
NetC6_2: C6.2 R8.2 Y1.2 | length 408.2
  Top Layer w10: C6.2@759,1060.79 Y1.2@841.79,1060.79 ; C6.2@761.77,1067.77 ccw(c778.62,1084.62) 778.62,1060.79 ; C6.2@768.84,1057.16 cw(c777.59,1048.41) 777.59,1060.79 ; C6.2@768.84,1074.84 ccw(c802.76,1108.77) 802.76,1060.79 ; 789.39,1060.79 cw(c789.39,1021.92) Y1.2@816.87,1049.4 ; 794.21,1060.79 ccw(c794.21,1092.83) Y1.2@816.87,1070.17 ; Y1.2@843,1060.79 R8.2@924.79,1060.79 ; Y1.2@869.13,1049.4 cw(c896.61,1021.92) 896.61,1060.79 ; Y1.2@869.13,1070.17 ccw(c891.79,1092.83) 891.79,1060.79 ; 887.24,1060.79 ccw(c887.24,1108.77) R8.2@921.16,1074.84 ; 911.38,1060.79 ccw(c911.38,1084.62) R8.2@928.23,1067.77 ; 912.41,1060.79 cw(c912.41,1048.41) R8.2@921.16,1057.16
NetC8_1: C8.1 R5.1 | length 178.8
  Bottom Layer w10: C8.1@1830,2370 R5.1@1914,2370 ; C8.1@1838.84,2361.16 cw(c1860.18,2339.82) 1860.18,2370 cw(c1860.18,2400.18) C8.1@1838.84,2378.84 ; R5.1@1905.16,2361.16 ccw(c1883.82,2339.82) 1883.82,2370 ccw(c1883.82,2400.18) R5.1@1905.16,2378.84
NetC11_1: C11.1 R9.1 Y2.1 | length 578.8
  Top Layer w10: Y2.1@721.72,891.82 ccw(c680.5,939.59) C11.1@743.6,939.59 ; Y2.1@728.25,884.25 ccw(c699.34,917.76) 743.6,917.76 ; C11.1@730.16,937.16 cw(c697.72,904.72) 743.6,904.72 ; C11.1@737.23,944.23 cw(c721.87,928.86) C11.1@743.6,928.86 ; C11.1@739,958.5 ccw(c739,979.02) 753.51,964.51 ; Y2.1@743.6,875.28 C11.1@743.6,939.6 ; 743.6,926.92 cw(c758.08,926.92) C11.1@747.84,937.16 ; C11.1@751.5,946 cw(c791.34,946) 763.17,974.17 ; R9.1@894.16,879.84 ccw(c872.82,901.18) 903,901.18 ccw(c933.18,901.18) R9.1@911.84,879.84 ; R9.1@903,871 903,923 843,983 772,983 750,961 750,946 C11.1@743.6,939.6
NetC12_1: C12.1 R10.1 Y2.3 | length 419
  Top Layer w10: C12.1@790.16,721.84 ccw(c748.54,763.46) Y2.3@807.4,763.46 ; Y2.3@795.63,769.01 cw(c767.2,740.58) 807.4,740.58 cw(c847.61,740.58) Y2.3@819.18,769.01 ; C12.1@797.23,714.77 ccw(c772.68,739.32) 807.4,739.32 ; C12.1@799,713 807.4,721.4 Y2.3@807.4,784.72 ; Y2.3@810,776.32 818.4,784.72 R10.1@902.72,784.72 ; Y2.3@819.18,772.95 cw(c847.61,744.52) 847.61,784.72 cw(c847.61,824.93) Y2.3@819.18,796.5 ; 872.16,784.72 ccw(c872.16,815.84) R10.1@894.16,793.84 ; 873.48,784.72 cw(c873.48,755.48) R10.1@894.16,776.16 ; R10.1@914.72,792.72 R10.1@915,793
NetC22_2: C22.2 C28.2 U3.32 | length 369.8
  Top Layer w10: U3.32@1447.9,2851.61 1459.39,2851.61 1543.5,2767.5 1547,2764 C28.2@1633,2764 ; U3.32@1448.26,2849.28 cw(c1453.89,2843.65) 1453.89,2851.61 ; 1522.42,2788.58 ccw(c1554,2820.16) C22.2@1554,2775.5 ; C22.2@1536.9,2774.1 cw(c1525.81,2763) C22.2@1541.5,2763 ; C22.2@1562.84,2754.16 cw(c1586.59,2730.41) 1586.59,2764 ; C22.2@1562.84,2771.84 ccw(c1581.76,2790.76) 1581.76,2764 ; 1605.41,2764 cw(c1605.41,2730.41) C28.2@1629.16,2754.16 ; 1610.24,2764 ccw(c1610.24,2790.76) C28.2@1629.16,2771.84
NetC24_2: C24.2 R1.1 R2.2 U1.9 | length 581.1
  Top Layer w10: U1.9@1120.14,1035.53 1206.54,1035.53 v3@1218.01,1047
  Bottom Layer w10: v3(1219,1048) 1232,1061 1232,1176 C24.2@1267,1211 ; C24.2@1254.5,1211 cw(c1224.32,1211) 1245.66,1189.66 cw(c1267,1168.32) C24.2@1267,1198.5 ; R1.1@1338,1290 R1.1@1341,1293
  Bottom Layer w20: R2.2@1250.3,1287.7 cw(c1263.11,1274.89) 1263.11,1293 cw(c1263.11,1311.11) R2.2@1250.3,1298.3 ; C24.2@1267,1211 1245,1233 R2.2@1245,1293 R1.1@1341,1293 ; R1.1@1335.7,1287.7 ccw(c1322.89,1274.89) 1322.89,1293 ccw(c1322.89,1311.11) R1.1@1335.7,1298.3
NetC27_2: C27.2 R36.2 U5.2 | length 601.5
  Bottom Layer w10: U5.2@1619,1901 U5.2@1619,1933.95 U5.2@1619,1941
  Bottom Layer w20: U5.2@1610.76,1962.86 ccw(c1590.87,1982.76) 1619,1982.76 ccw(c1647.13,1982.76) U5.2@1627.24,1962.86 ; U5.2@1619,1901 1707,1813 R36.2@1707,1800 ; U5.2@1619,1941 1619,2001 1646,2028 C27.2@1815,2028 ; U5.2@1630.65,1913.28 ccw(c1688.44,1913.28) 1647.58,1872.42 ; 1686,1834 cw(c1651,1799) R36.2@1700.5,1799 ; C27.2@1809.7,2022.7 ccw(c1796.89,2009.89) 1796.89,2028 ccw(c1796.89,2046.11) C27.2@1809.7,2033.3
NetCN1_33: CN1.33 R16.1 | length 1568.9
  Top Layer w10: v1@394.58,961.42 574.42,961.42 v1(591,978) ; v1@399.82,956.18 cw(c412.45,943.55) 412.45,961.42 ; v1@399.82,965.82 ccw(c410.44,976.44) 410.44,961.42 ; v1@584.19,978 cw(c567.75,978) 579.37,966.37 cw(c591,954.75) v1@591,971.19
  Bottom Layer w10: CN1.33@148,799 148,800.17 197.42,849.58 ; CN1.33@148.67,820.41 ccw(c150.04,864.27) 181.07,833.24 ; CN1.33@148.98,830.4 ccw(c151.04,895.96) 197.41,849.58 ; CN1.33@169.36,800.5 cw(c212.45,803.53) 181.91,834.07 ; CN1.33@179.34,801.21 cw(c241.42,805.57) 197.41,849.58 ; v1@390.18,956.18 ccw(c378.56,944.56) 378.56,961 ccw(c378.56,977.44) v1@390.18,965.82 ; v1(395,961) 297,961 286,950 217,950 197.42,930.42 197.42,849.58 ; v1(591,978) 609,996 609,1107 688,1186 741,1186 809,1254 1041,1254 R16.1@1072,1223 ; v1@591,984.81 ccw(c591,1001.25) 602.63,989.63 ccw(c614.25,978) v1@597.81,978 ; 1049.54,1245.46 ccw(c1076,1271.92) R16.1@1076,1234.5 ; 1056.78,1238.22 cw(c1040.56,1222) R16.1@1063.5,1222
NetCN1_35: CN1.35 R17.1 | length 1610.9
  Top Layer w10: v1@537,868.81 ccw(c537,885.25) 548.63,873.63 ccw(c560.25,862) v1@543.81,862 ; v1@538,863 v1(603,928) ; v1@596.19,928 cw(c579.75,928) 591.37,916.37 cw(c603,904.75) v1@603,921.19
  Bottom Layer w10: CN1.35@149.17,699 CN1.35@148,699 197.42,748.42 ; CN1.35@149.28,720.38 ccw(c151.79,762.58) 181.69,732.69 ccw(c211.58,702.79) CN1.35@169.38,700.28 ; CN1.35@149.87,730.36 ccw(c153.56,792.27) 197.42,748.42 ; CN1.35@179.36,700.87 cw(c241.27,704.56) 197.42,748.42 ; v1@530.19,862 cw(c513.75,862) 525.37,850.37 cw(c537,838.75) v1@537,855.19 ; v1(537,862) 451,776 352,776 324.42,748.42 197.42,748.42 ; v1(603,928) 636,961 636,1091 709,1164 769,1164 834,1229 909,1229 ; v1@603,934.81 ccw(c603,951.25) 614.63,939.63 ccw(c626.25,928) v1@609.81,928 ; 881,1229 909,1229 ; 1049.54,1163.46 ccw(c1076,1189.92) R17.1@1076,1152.5 ; 1056.78,1156.22 cw(c1040.56,1140) R17.1@1063.5,1140 ; R17.1@1072,1141 984,1229 909,1229
NetCN1_37: CN1.37 R18.1 | length 2180.4
  Top Layer w10: CN1.37@148,599 CN1.37@149.17,599
  Bottom Layer w10: CN1.37@148,599 197.42,648.42 ; CN1.37@149.28,620.38 ccw(c151.79,662.58) 181.69,632.69 ccw(c211.58,602.79) CN1.37@169.38,600.28 ; CN1.37@149.87,630.36 ccw(c153.56,692.27) 197.42,648.42 ; CN1.37@179.36,600.87 cw(c241.27,604.56) 197.42,648.42 ; 988,291 988,361 ; 1082.41,720 cw(c1082.41,686.41) R18.1@1106.16,710.16 ; 1087.24,720 ccw(c1087.24,746.76) R18.1@1106.16,727.84 ; R18.1@1113,720 1048,720 988,660 988,361 ; 197.42,648.42 309.58,648.42 359,599 359,193 395,157 870,157 988,275 988,361
NetCN1_39: CN1.39 R19.1 | length 2020.1
  Bottom Layer w10: CN1.39@148,499 198,549 ; CN1.39@149.09,520.39 ccw(c151.3,563.87) 182.08,533.08 ccw(c212.87,502.3) CN1.39@169.39,500.09 ; CN1.39@149.6,530.38 ccw(c152.84,594.15) 198,549 ; CN1.39@179.38,500.6 cw(c243.15,503.84) 198,549 ; 1033,276 1033,283 ; 1082.41,636 cw(c1082.41,602.41) R19.1@1106.16,626.16 ; 1087.24,636 ccw(c1087.24,662.76) R19.1@1106.16,643.84 ; R19.1@1113,636 1054,636 1033,615 1033,283 ; 198,549 294,549 321,522 321,189 378,132 932,132 1033,233 1033,283
NetCN1_44: CN1.44 CN3.5 R20.1 R23.2 | length 1382.8
  Top Layer w10: CN1.44@248,299 330,299 343,312 CN3.5@429,312 CN3.5@416,299 ; CN1.44@263.14,283.86 cw(c299.71,247.29) 299.71,299 cw(c299.71,350.71) CN1.44@263.14,314.14 ; CN1.44@270.22,276.78 cw(c323.85,223.15) 323.85,299 cw(c323.85,374.85) CN1.44@270.22,321.22 ; CN3.5@406.78,289.78 ccw(c353.15,236.15) 353.15,312 ccw(c353.15,387.85) CN3.5@406.78,334.22 ; CN3.5@413.86,296.86 ccw(c377.29,260.29) 377.29,312 ccw(c377.29,363.71) CN3.5@413.86,327.14
  Bottom Layer w10: CN3.5@429,312 654,312 745,403 R23.2@745,484 ; CN3.5@444.14,296.86 cw(c480.71,260.29) 480.71,312 cw(c480.71,363.71) CN3.5@444.14,327.14 ; CN3.5@451.22,289.78 cw(c504.85,236.15) 504.85,312 cw(c504.85,387.85) CN3.5@451.22,334.22 ; 722.25,380.25 cw(c747,355.5) R20.1@747,390.5 ; 727.07,385.07 ccw(c709.15,403) R20.1@734.5,403 ; R20.1@738.16,411.84 ccw(c721.65,428.35) 745,428.35 ; R23.2@738.16,483.16 cw(c721.65,466.65) 745,466.65 ; 745,438.01 ccw(c782.01,438.01) R20.1@755.84,411.84 ; 745,456.99 cw(c782.01,456.99) R23.2@755.84,483.16
NetCN1_46: CN1.46 CN3.6 R21.1 R22.2 | length 1362
  Top Layer w10: CN1.46@248,199 330,199 343,212 CN3.6@429,212 ; CN1.46@263.14,183.86 cw(c299.71,147.29) 299.71,199 cw(c299.71,250.71) CN1.46@263.14,214.14 ; CN1.46@270.22,176.78 cw(c323.85,123.15) 323.85,199 cw(c323.85,274.85) CN1.46@270.22,221.22 ; CN3.6@406.78,189.78 ccw(c353.15,136.15) 353.15,212 ccw(c353.15,287.85) CN3.6@406.78,234.22 ; CN3.6@413.86,196.86 ccw(c377.29,160.29) 377.29,212 ccw(c377.29,263.71) CN3.6@413.86,227.14 ; CN3.6@423,199 CN3.6@429,205
  Bottom Layer w10: CN3.6@429,212 741,212 R21.1@745,216 ; CN3.6@444.14,196.86 cw(c480.71,160.29) 480.71,212 cw(c480.71,263.71) CN3.6@444.14,227.14 ; CN3.6@451.22,189.78 cw(c504.85,136.15) 504.85,212 cw(c504.85,287.85) CN3.6@451.22,234.22 ; 704.75,212 ccw(c704.75,259.25) 738.16,225.84 ccw(c716.82,247.18) 747,247.18 ccw(c777.18,247.18) R21.1@755.84,225.84 ; R21.1@738.16,208.16 ccw(c728.9,198.9) 728.9,212 ccw(c728.89,235.11) R21.1@745.23,218.77 ; R22.2@738.16,296.16 cw(c716.82,274.82) 747,274.82 cw(c777.18,274.82) R22.2@755.84,296.16 ; R21.1@747,216 R22.2@747,304
NetCN2_1: CN2.1 R24.2 | length 393.7
  Bottom Layer w10: CN2.1@428,1600 CN2.1@433,1605 ; CN2.1@429,1612 558,1612 R24.2@565,1605 ; CN2.1@444.14,1596.86 cw(c480.71,1560.29) 480.71,1612 cw(c480.71,1663.71) CN2.1@444.14,1627.14 ; CN2.1@451.22,1589.78 cw(c504.85,1536.15) 504.85,1612 cw(c504.85,1687.85) CN2.1@451.22,1634.22 ; 528.41,1612 cw(c528.41,1578.41) R24.2@552.16,1602.16 ; 533.24,1612 ccw(c533.24,1638.76) R24.2@552.16,1619.84
NetCN4_8: CN4.8 CN6.15 R26.2 | length 1130.9
  Bottom Layer w10: R26.2@2218.7,1785.7 ccw(c2256.59,1823.59) 2256.59,1770 ; R26.2@2225,1790 2245,1770 2328,1770 2457,1770 CN6.15@2528,1699 CN6.15@2522,1699 ; R26.2@2225.77,1792.77 ccw(c2280.74,1847.74) 2280.74,1770 ; R26.2@2232.84,1799.84 ccw(c2304.88,1871.88) CN4.8@2304.88,1770 ; 2248.32,1770 ccw(c2248.32,1852.68) CN4.8@2306.78,1794.22 ; 2257.98,1770 cw(c2257.98,1700.98) CN4.8@2306.78,1749.78 ; 2272.47,1770 ccw(c2272.47,1828.53) CN4.8@2313.86,1787.14 ; 2282.12,1770 cw(c2282.12,1725.12) CN4.8@2313.86,1756.86 ; CN4.8@2344.14,1756.86 cw(c2375.88,1725.12) 2375.88,1770 ; CN4.8@2344.14,1787.14 ccw(c2385.53,1828.53) 2385.53,1770 ; CN4.8@2351.22,1749.78 cw(c2400.02,1700.98) 2400.02,1770 ; CN4.8@2351.22,1794.22 ccw(c2409.68,1852.68) 2409.68,1770 ; CN6.15@2496.58,1699 ccw(c2420.73,1699) 2474.37,1752.63 ccw(c2528,1806.27) CN6.15@2528,1730.42 ; CN6.15@2506.58,1699 ccw(c2454.88,1699) 2491.44,1735.56 ccw(c2528,1772.12) CN6.15@2528,1720.42
NetCN6_44: CN6.44 R27.2 | length 635.1
  Bottom Layer w10: R27.2@2225.58,362.58 2401.42,362.58 2415,349 2562,349 2612,299 CN6.44@2628,299 ; R27.2@2233.84,353.16 cw(c2256.58,330.42) 2256.58,362.58 ; R27.2@2233.84,370.84 ccw(c2253.77,390.77) 2253.77,362.58 ; 2570,341 ccw(c2604.26,375.26) CN6.44@2618.66,329 ; 2581.7,329.3 ccw(c2609.82,357.41) CN6.44@2621.63,319.45 ; 2585.68,325.32 cw(c2559.36,299) CN6.44@2596.58,299 ; 2593.4,317.6 ccw(c2615.37,339.56) CN6.44@2624.61,309.9
NetD1_1: D1.1 R14.1 | length 222.4
  Top Layer w10: v1(1251,2354) D1.1@1289,2354 ; v1@1255.82,2349.18 cw(c1267.44,2337.56) 1267.44,2354 cw(c1267.44,2370.44) v1@1255.82,2358.82 ; v1@1262.03,2354 cw(c1262.03,2323.03) D1.1@1283.93,2344.93 ; 1271.69,2354 ccw(c1271.69,2371.31) D1.1@1283.93,2359.07 ; D1.1@1291,2352 D1.1@1291,2354
  Bottom Layer w10: R14.1@1206,2353 1207,2354 v1(1251,2354) ; R14.1@1214.84,2344.16 cw(c1238.59,2320.41) 1238.59,2354 ; R14.1@1214.84,2361.84 ccw(c1233.77,2380.77) 1233.77,2354 ; v1@1246.18,2349.18 ccw(c1234.56,2337.56) 1234.56,2354 ccw(c1234.56,2370.44) v1@1246.18,2358.82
